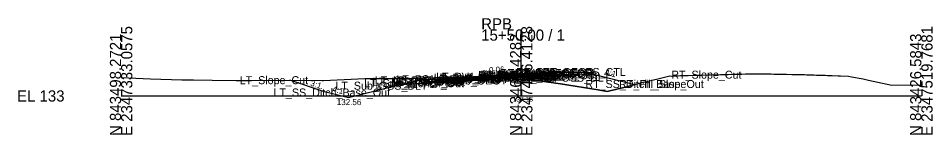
# Model space of a CAD drawing. Extents: x -76 to 2347760, y -10 to 844216.
# Drawn here: x -25.7 to 202.8, y 490.3 to 519.4 of the extents above; entities that cross this region are included whole.
import ezdxf

# ---------------------------------------------------------------- set-up
doc = ezdxf.new("R2010")
doc.units = 0
for name, color, linetype in [('Default', 7, 'Continuous'), ('Exist Cross Section Cell', 7, 'Continuous'), ('Exist XS Center Line Elevation Label', 7, 'Continuous'), ('Exist XS Ground Line', 7, 'Continuous'), ('Prop CMT Pvmt Course 1', 7, 'Continuous'), ('Prop CMT Pvmt Course 2', 7, 'Continuous'), ('Prop CMT Pvmt Course 3', 7, 'Continuous'), ('Prop CMT Pvmt Surface', 7, 'Continuous'), ('Prop CMT Pvmt Surface Shoulder', 7, 'Continuous'), ('Prop CMT Shld Paved Course 1', 7, 'Continuous'), ('Prop CMT Shld Paved Course 2', 7, 'Continuous'), ('Prop CMT Shld Paved Course 3', 7, 'Continuous'), ('Prop CMT Slope Grass', 7, 'Continuous'), ('Prop CMT Subgrade Earthwork', 7, 'Continuous'), ('Prop XS Ditch Standard Text', 7, 'Continuous'), ('Prop XS Earthwork Shape', 7, 'Continuous'), ('Prop XS SE Text', 7, 'Continuous'), ('Prop XS Side Slope Text', 7, 'Continuous'), ('Scratch_Level_0', 7, 'Continuous')]:
    doc.layers.add(name, color=color, linetype=linetype)

msp = doc.modelspace()

# ---------------------------------------------------------------- linework, layer by layer
at = {"layer": 'Exist Cross Section Cell'}
for p, q in [((100, 500), (100, 516.63)), ((0, 500), (100, 500)), ((100, 500), (200, 500))]:
    msp.add_line(p, q, dxfattribs=at)
at = {"layer": 'Exist XS Ground Line'}
msp.add_lwpolyline([(0, 504.62), (7.37, 504.3), (15.19, 504.07), (18.08, 504), (22.72, 503.92), (28.79, 503.85), (32.58, 503.87), (39.5, 503.96), (50.22, 503.87), (50.62, 503.88), (60.93, 504.36), (67.35, 504.35), (71.64, 504.41), (78.52, 504.58), (82.35, 504.73), (84.74, 504.67), (93.06, 504.69), (100, 504.16), (102.13, 504), (103.78, 503.91), (104.51, 503.82), (109.8, 503.01), (119.26, 501.56), (119.66, 501.49), (121.45, 501.12), (125.97, 502.22), (130.55, 503.47), (134.16, 504.27), (137.15, 505.02), (137.59, 504.98), (138.01, 505), (139.26, 505.07), (139.8, 505.09), (141.22, 505.13), (141.76, 505.14), (142.99, 505.18), (144.44, 505.23), (145.06, 505.24), (146.9, 505.3), (147.32, 505.3), (149.78, 505.36), (151.72, 505.41), (152.45, 505.43), (153.65, 505.45), (154.73, 505.48), (155.13, 505.48), (156.03, 505.5), (157.82, 505.54), (158.8, 505.54), (160.61, 505.53), (162.43, 505.5), (163.14, 505.49), (164.41, 505.48), (165.85, 505.45), (166.32, 505.44), (167.59, 505.41), (168.79, 505.38), (170.82, 505.34), (171.33, 505.32), (173.23, 505.26), (173.83, 505.24), (174.58, 505.22), (176, 505.17), (176.53, 505.15), (177.75, 505.1), (179.22, 505.04), (179.81, 505.02), (181.77, 504.92), (182.54, 504.78), (185.48, 504.26), (186.83, 503.97), (192.66, 502.72), (200, 502.81)], dxfattribs=at)
at = {"layer": 'Prop CMT Pvmt Course 1'}
for p, q in [((100, 505.51), (88, 504.79)), ((88, 504.54), (100, 505.26)), ((100, 505.51), (104, 505.75)), ((100, 505.26), (100, 505.51)), ((100, 505.26), (100, 505.51)), ((104, 505.5), (100, 505.26)), ((100, 505.26), (100, 505.39)), ((100, 505.39), (100, 505.39)), ((100, 505.39), (100, 505.26)), ((100, 505.26), (100, 505.39)), ((100, 505.39), (100, 505.39)), ((100, 505.39), (100, 505.26)), ((100, 505.26), (100, 505.26)), ((100, 505.26), (100, 505.26)), ((104, 505.75), (104, 505.5)), ((88, 504.79), (88, 504.54))]:
    msp.add_line(p, q, dxfattribs=at)
at = {"layer": 'Prop CMT Pvmt Course 2'}
for p, q in [((100, 505.26), (88, 504.54)), ((100, 505.26), (104, 505.5)), ((100, 504.93), (100, 505.26)), ((100, 504.93), (100, 505.26)), ((104, 505.17), (100, 504.93)), ((104, 505.5), (104, 505.17)), ((88, 504.21), (100, 504.93)), ((88, 504.54), (88, 504.21))]:
    msp.add_line(p, q, dxfattribs=at)
at = {"layer": 'Prop CMT Pvmt Course 3'}
for p, q in [((100, 504.93), (104, 505.17)), ((104, 505.17), (104, 504.83)), ((100, 504.93), (88, 504.21)), ((88, 503.87), (100, 504.59)), ((88, 504.21), (88, 503.87)), ((100, 504.59), (100, 504.93)), ((100, 504.59), (100, 504.93)), ((104, 504.83), (100, 504.59))]:
    msp.add_line(p, q, dxfattribs=at)
at = {"layer": 'Prop CMT Pvmt Surface'}
for q in [(88, 504.79), (104, 505.75)]:
    msp.add_line((100, 505.51), q, dxfattribs=at)
at = {"layer": 'Prop CMT Pvmt Surface Shoulder'}
for p, q in [((104, 505.75), (108, 505.99)), ((88, 504.79), (78, 504.19))]:
    msp.add_line(p, q, dxfattribs=at)
at = {"layer": 'Prop CMT Shld Paved Course 1'}
for p, q in [((104, 505.75), (108, 505.99)), ((108.24, 505.75), (104, 505.5)), ((104, 505.5), (104, 505.75)), ((108, 505.99), (108.24, 505.75)), ((77.73, 503.92), (88, 504.54)), ((78, 504.19), (77.73, 503.92)), ((88, 504.79), (78, 504.19)), ((88, 504.54), (88, 504.79))]:
    msp.add_line(p, q, dxfattribs=at)
at = {"layer": 'Prop CMT Shld Paved Course 2'}
for p, q in [((104, 505.5), (108.24, 505.75)), ((104, 505.17), (104, 505.5)), ((108.55, 505.44), (104, 505.17)), ((108.24, 505.75), (108.55, 505.44)), ((77.38, 503.57), (88, 504.21)), ((77.73, 503.92), (77.38, 503.57)), ((88, 504.54), (77.73, 503.92)), ((88, 504.21), (88, 504.54))]:
    msp.add_line(p, q, dxfattribs=at)
at = {"layer": 'Prop CMT Shld Paved Course 3'}
for p, q in [((104, 505.17), (108.55, 505.44)), ((104, 504.83), (104, 505.17)), ((109.36, 505.16), (104, 504.83)), ((108.55, 505.44), (109.05, 505.47)), ((109.05, 505.47), (109.36, 505.16)), ((76.52, 503.19), (88, 503.87)), ((76.88, 503.54), (76.52, 503.19)), ((77.38, 503.57), (76.88, 503.54)), ((88, 504.21), (77.38, 503.57)), ((88, 503.87), (88, 504.21))]:
    msp.add_line(p, q, dxfattribs=at)
at = {"layer": 'Prop CMT Slope Grass'}
for p, q in [((108, 505.99), (116, 505.99)), ((116, 505.99), (128.41, 502.89)), ((50.84, 501.06), (42.21, 503.94)), ((74.13, 503.88), (56.84, 499.56)), ((78, 504.19), (74.13, 503.88)), ((56.84, 499.56), (50.84, 501.06))]:
    msp.add_line(p, q, dxfattribs=at)
at = {"layer": 'Prop CMT Subgrade Earthwork'}
for p, q in [((104, 504.83), (117.41, 505.64)), ((76.52, 503.19), (69.71, 502.78)), ((88, 503.87), (76.52, 503.19)), ((100, 504.59), (88, 503.87)), ((100, 504.59), (104, 504.83))]:
    msp.add_line(p, q, dxfattribs=at)
at = {"layer": 'Prop XS Earthwork Shape'}
for points in [[(104, 504.83), (117.41, 505.64), (128.41, 502.89), (125.97, 502.22), (121.45, 501.12), (119.66, 501.49), (119.26, 501.56), (109.8, 503.01), (104.51, 503.82), (103.78, 503.91), (102.13, 504), (100, 504.16), (96.8, 504.4), (100, 504.59)], [(78, 504.19), (74.13, 503.88), (69.71, 502.78), (56.84, 499.56), (50.84, 501.06), (42.21, 503.94), (50.22, 503.87), (50.62, 503.88), (60.93, 504.36), (67.35, 504.35), (71.64, 504.41), (78.52, 504.58), (82.35, 504.73), (84.74, 504.67), (86.05, 504.67)], [(76.52, 503.19), (69.71, 502.78), (74.13, 503.88), (78, 504.19), (86.05, 504.67), (93.06, 504.69), (96.8, 504.4), (88, 503.87)]]:
    msp.add_lwpolyline(points, close=True, dxfattribs=at)

# ---------------------------------------------------------------- texts
at = {"layer": 'Default'}
msp.add_text('-', height=0.0001, dxfattribs=at).set_placement((0, 500))
at = {"layer": 'Exist Cross Section Cell'}
for s, p in [('RPB', (90, 516.63)), ('15+50.00 / 1', (90, 513.83)), ('EL 133', (-26, 498.6))]:
    msp.add_text(s, height=2.8, dxfattribs=at).set_placement(p)
for s, p in [('E 2347333.0575', (2.8, 490)), ('E 2347426.4128', (102.8, 490)), ('E 2347519.7681', (202.8, 490)), ('N 843498.2721', (0, 490)), ('N 843462.4282', (100, 490)), ('N 843426.5843', (200, 490))]:
    msp.add_text(s, height=2.8, rotation=90, dxfattribs=at).set_placement(p)
at = {"layer": 'Exist XS Center Line Elevation Label'}
msp.add_text('137.16', height=1.2, dxfattribs=at).set_placement((97.86, 498.56))
at = {"layer": 'Prop XS Ditch Standard Text'}
msp.add_text('132.56', height=1.5, dxfattribs=at).set_placement((53.91, 497.71))
at = {"layer": 'Prop XS SE Text'}
for s, rotation, p in [('0.06', 3.4336, (91.98, 505.69)), ('3:1', 341.5651, (47.16, 502.6)), ('4:1', 14.0362, (63.77, 501.71))]:
    msp.add_text(s, height=1.5, rotation=rotation, dxfattribs=at).set_placement(p)
at = {"layer": 'Prop XS Side Slope Text'}
for p in [(120.81, 505.36), (52.69, 501.12)]:
    msp.add_text('4:1', height=1.5, rotation=345.5351, dxfattribs=at).set_placement(p)
at = {"layer": 'Scratch_Level_0'}
for s, p in [('LT_Slope_Cut', (29.64, 502.95)), ('LT_PS1_OEOP', (68.8, 503.19)), ('LT_PV2_OEOT', (78.17, 503.54)), ('LT_PV3_OEOT', (78.17, 503.21)), ('LT_PV1_OEOT', (78.74, 503.79)), ('RT_Sub_OEEOP', (89.17, 503.59)), ('LT_Sub_OEEOP', (89.21, 503.59)), ('RT_PV2_OEEOP', (89.26, 504.26)), ('RT_PV3_OEEOP', (89.26, 503.93)), ('LT_PV2_OEEOP', (89.31, 504.26)), ('LT_PV3_OEEOP', (89.31, 503.93)), ('RT_PV1_OEEOP', (89.83, 504.39)), ('LT_PV1_OEEOP', (89.87, 504.39)), ('RT_PV2_IEEOP', (89.91, 504.26)), ('LT_PV2_IEEOP', (89.95, 504.26)), ('RT_PV1_IEEOP', (90.47, 504.39)), ('LT_PV1_IEEOP', (90.52, 504.39)), ('RT_Sub_Trench_Out', (93.52, 504.16)), ('PV2_PGL', (93.91, 504.26)), ('RT_Sub_OEOT', (94.03, 503.83)), ('RT_PV2_OEOT', (94.13, 504.5)), ('RT_PV3_OEOT', (94.13, 504.17)), ('PV1_PGL', (94.47, 504.51)), ('RT_PV1_OEOT', (94.69, 504.75)), ('RT_PS3_Shelf_Out', (94.99, 504.47)), ('RT_PS2_OEOP', (98.42, 504.75)), ('RT_PS3_OEOP', (98.74, 504.44)), ('RT_Sub_OSS_DLT', (98.75, 503.57)), ('RT_PS1_OEOP', (98.76, 504.99)), ('RT_GS_OS_CTL', (105.32, 504.99)), ('RT_Slope_Cut', (137.51, 504.32)), ('LT_Sub_OSS_DLT', (53.56, 501.56)), ('LT_Sub_Trench_Out', (60.73, 502.19)), ('LT_PS3_Shelf_Out', (62.86, 502.54)), ('LT_GS_OS_CTL', (63.37, 502.87)), ('LT_PS3_OEOP', (67.62, 502.57)), ('LT_PS2_OEOP', (67.97, 502.92)), ('LT_Sub_OEOT', (78.08, 502.87)), ('RT_SS_Ditch_Base_Out', (116.03, 501.99)), ('RT_Fill_Slope', (124.47, 501.99)), ('LT_SS_Ditch_Base_Out', (38.08, 499.87))]:
    msp.add_text(s, height=2, dxfattribs=at).set_placement(p)

doc.saveas('drawing.dxf')
